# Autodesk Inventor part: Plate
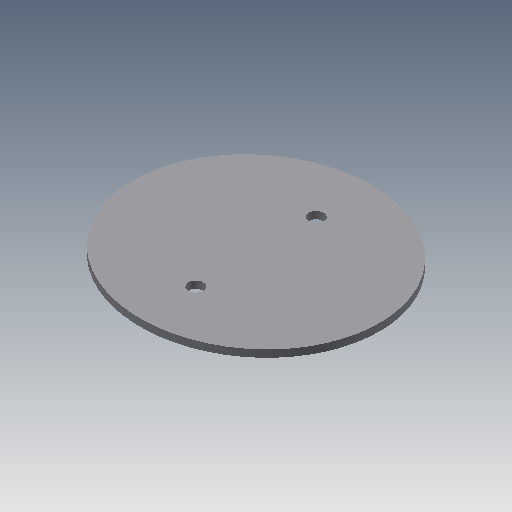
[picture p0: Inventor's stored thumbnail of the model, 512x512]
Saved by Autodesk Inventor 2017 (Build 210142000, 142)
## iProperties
Created: 2009-04
Part Number: Plate
Document SubType Name: Modeling
Designer: Sham
Density: 1 g/cm^3
Material: Generic
Appearance: Default
Author: Sham
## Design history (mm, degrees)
sketch "Sketch1"
  geometry: C1 r 6.25 at (-50, 0); C2 r 6.25 at (50, 0); 4 further points; 1 other entity
  constraints: 2 centre point, 1 coincident, 5 other
  dimensions: "d1" = 12.5 diameter of C1; "d2" = 12.5 diameter of C2; "d3" = 100 distance of C2.centre C1.centre; "d4" = 102.5 distance of point (0, 0) point (0, 102.5); "d5" = 96 distance of point (0, 0) point (-96, 0); "d6" = 50 distance of point (0, 0) C1.centre
extrude "Extrusion1" new body sketch "Sketch1" distance "d7" = 6; taper "d8" = 0 deg
body "Solid1"
